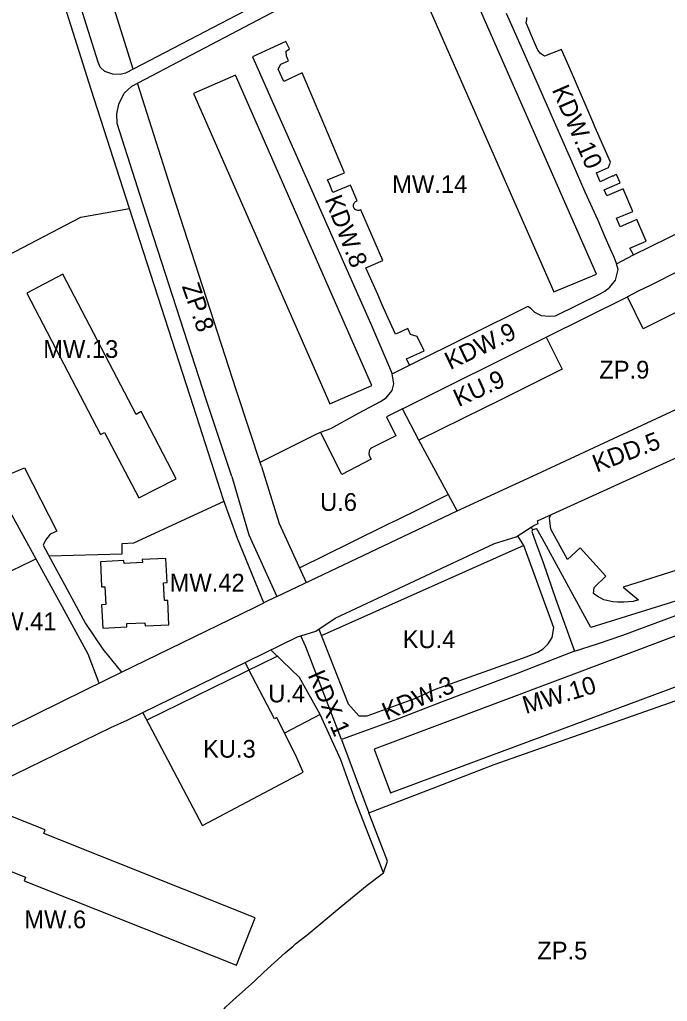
# Model space of a CAD drawing. Extents: x 7426178 to 7427732, y 5548847 to 5550287.
# Drawn here: x 7427061.4 to 7427225.9, y 5549279.8 to 5549528.9 of the extents above; entities that cross this region are included whole.
import ezdxf

# ---------------------------------------------------------------- set-up
doc = ezdxf.new("R2010")
doc.units = 0
for name, color, linetype in [('linie_rozgraniczajace', 7, 'Continuous'), ('linie_zabudowy_nieprzekraczalne', 7, 'Continuous'), ('linie_zabudowy_obowiazujace', 7, 'Continuous'), ('oznaczenia_przeznaczen', 7, 'Continuous')]:
    doc.layers.add(name, color=color, linetype=linetype)

msp = doc.modelspace()

# ---------------------------------------------------------------- linework, layer by layer
at = {"layer": 'linie_rozgraniczajace'}
for p, q in [((7427135.84, 5549509.04), (7427135.84, 5549509.04)), ((7427137.28, 5549505.68), (7427137.28, 5549505.68)), ((7427207.86, 5549500.83), (7427207.48, 5549501.69)), ((7427207.48, 5549501.69), (7427207.48, 5549501.69)), ((7427207.86, 5549500.83), (7427207.86, 5549500.83)), ((7427217.26, 5549469.25), (7427217.26, 5549469.25)), ((7427195.07, 5549448.37), (7427215.71, 5549458.63)), ((7427153.46, 5549456.57), (7427153.46, 5549456.57)), ((7427157.28, 5549449.31), (7427157.28, 5549449.31)), ((7427160.34, 5549441.22), (7427160.34, 5549441.22)), ((7427137.79, 5549424.28), (7427137.79, 5549424.28)), ((7427172.51, 5549404.3), (7427162.71, 5549422.19)), ((7427191.25, 5549400.11), (7427191.64, 5549399.49)), ((7427194.14, 5549397.18), (7427194.14, 5549397.18)), ((7427126.71, 5549382.6), (7427123.34, 5549380.95)), ((7427107.8, 5549324.47), (7427092.66, 5549353.13)), ((7427137.66, 5549352.59), (7427128.65, 5549347.91)), ((7427149.84, 5549348.75), (7427143.11, 5549346.29)), ((7427143.11, 5549346.29), (7427150.02, 5549327.69)), ((7427107.8, 5549324.47), (7427133.41, 5549338))]:
    msp.add_line(p, q, dxfattribs=at)
for points in [[(7427090.22, 5549516.36), (7427081.87, 5549542.92), (7427081.79, 5549544.97), (7427082.46, 5549552.09), (7427088.15, 5549602.17), (7427088.49, 5549610.35), (7427086.67, 5549624.17), (7427084.42, 5549632.79), (7427081.45, 5549642.76)], [(7427230.48, 5549589.38), (7427148.85, 5549546.95), (7427088.25, 5549515.33), (7427086.86, 5549515.01), (7427085.02, 5549515.09), (7427083.04, 5549515.77), (7427081.79, 5549516.82), (7427081.29, 5549518.09), (7427073.92, 5549541.54), (7427073.78, 5549545.19), (7427074.5, 5549552.91), (7427080.17, 5549602.79), (7427080.47, 5549609.99), (7427078.8, 5549622.63), (7427076.71, 5549630.64), (7427074.28, 5549638.8)], [(7427115.22, 5549413.02), (7427108.83, 5549432.27), (7427108.83, 5549432.27), (7427092.63, 5549482.16), (7427086.13, 5549502.57), (7427086.04, 5549505.04), (7427086.55, 5549507.51), (7427087.93, 5549510.29), (7427089.87, 5549512.02), (7427150.51, 5549543.92), (7427232.16, 5549586.41)], [(7427123.34, 5549380.95), (7427116.69, 5549397.29), (7427113.13, 5549407.11), (7427105.56, 5549430.76), (7427089.3, 5549481.03), (7427079.5, 5549511.18), (7427070.38, 5549540.22), (7427070.06, 5549553.47)], [(7427184.96, 5549530.59), (7427189.29, 5549520.68), (7427192.88, 5549512.63), (7427195.68, 5549506.27), (7427198.65, 5549499.56), (7427201.58, 5549492.85), (7427204.93, 5549485.26), (7427208.17, 5549478.05), (7427209.98, 5549473.84), (7427211.22, 5549470.95), (7427212.15, 5549468.89), (7427212.94, 5549467)], [(7427207.48, 5549501.69), (7427206.91, 5549502.99), (7427201.73, 5549515.02), (7427199.01, 5549521.35), (7427194.68, 5549519.69), (7427193.63, 5549520.34), (7427192.93, 5549521.15), (7427192.07, 5549523.26), (7427189.97, 5549528.11), (7427190.16, 5549528.92)], [(7427135.84, 5549509.04), (7427133.08, 5549515.46), (7427128.44, 5549513.26), (7427127.04, 5549516.38), (7427127.69, 5549517.61), (7427129.67, 5549518.51), (7427129.18, 5549519.69), (7427129.04, 5549520.96), (7427129.94, 5549521.5), (7427128.97, 5549523.39), (7427124.9, 5549521.5), (7427120.53, 5549519.45), (7427121.61, 5549517.02), (7427125.18, 5549508.99)], [(7427122.81, 5549415.54), (7427116.43, 5549434.77), (7427100.25, 5549484.61), (7427091.28, 5549512.76)], [(7427125.18, 5549508.99), (7427130.55, 5549496.81), (7427135.24, 5549486.35), (7427143.87, 5549466.83), (7427150.46, 5549451.93), (7427154.78, 5549441.85), (7427155.97, 5549439.08)], [(7427137.28, 5549505.68), (7427137.2, 5549505.87), (7427135.84, 5549509.04)], [(7427135.84, 5549509.04), (7427135.84, 5549509.04)], [(7427153.46, 5549456.57), (7427152.31, 5549459.17), (7427149.28, 5549465.93), (7427153.62, 5549467.83), (7427148.02, 5549480.65), (7427147.47, 5549480.49), (7427147.28, 5549480.47), (7427147.01, 5549480.54), (7427146.78, 5549480.66), (7427146.6, 5549480.77), (7427146.43, 5549480.96), (7427146.27, 5549481.18), (7427146.13, 5549481.55), (7427146.15, 5549481.91), (7427146.24, 5549482.22), (7427146.4, 5549482.51), (7427146.64, 5549482.74), (7427146.95, 5549482.9), (7427147.06, 5549482.93), (7427145.39, 5549486.91), (7427140.93, 5549485.02), (7427140.11, 5549486.99), (7427139.59, 5549488.25), (7427143.88, 5549490.08), (7427137.28, 5549505.68)], [(7427137.28, 5549505.68), (7427137.28, 5549505.68)], [(7427207.48, 5549501.69), (7427207.48, 5549501.69)], [(7427212.04, 5549489.25), (7427208.82, 5549487.77), (7427207.84, 5549490.02), (7427210.88, 5549491.38), (7427211.4, 5549492.79), (7427207.86, 5549500.83)], [(7427207.86, 5549500.83), (7427207.86, 5549500.83)], [(7427217.26, 5549469.25), (7427216.32, 5549470.93), (7427220.46, 5549472.71), (7427218.14, 5549478.18), (7427213.9, 5549476.35), (7427212.97, 5549478.51), (7427217.08, 5549480.26), (7427214.67, 5549486.03), (7427210.46, 5549484.18), (7427209.81, 5549485.7), (7427213.85, 5549487.51), (7427212.92, 5549489.65), (7427212.43, 5549489.43)], [(7427137.79, 5549424.28), (7427140.37, 5549425.18), (7427147.44, 5549429.1), (7427153.02, 5549432.02), (7427154.49, 5549432.94), (7427156, 5549434.84), (7427156.43, 5549436.51), (7427155.97, 5549439.08), (7427160.34, 5549441.22), (7427190.47, 5549456.21), (7427191.08, 5549455.72), (7427192.08, 5549454.67), (7427193.85, 5549453.84), (7427195.91, 5549453.65), (7427197.48, 5549453.77), (7427208.78, 5549459.32), (7427210, 5549460.06), (7427211.22, 5549461.02), (7427212.72, 5549462.85), (7427213.35, 5549465.51), (7427212.94, 5549467), (7427217.26, 5549469.25), (7427248.33, 5549484.49)], [(7427039.88, 5549459.54), (7427076.89, 5549478.82), (7427089.3, 5549481.03)], [(7427254.85, 5549478.08), (7427251.88, 5549476.6), (7427246.33, 5549473.85), (7427243.64, 5549472.52), (7427240.95, 5549471.19), (7427238.26, 5549469.86), (7427235.39, 5549468.41), (7427232.25, 5549466.85), (7427229.34, 5549465.41), (7427226.67, 5549464.08), (7427223.99, 5549462.75), (7427221.31, 5549461.42), (7427218.63, 5549460.09), (7427215.71, 5549458.63)], [(7427258.91, 5549469.96), (7427239.47, 5549460.24), (7427236.31, 5549458.73), (7427219.73, 5549450.51), (7427215.71, 5549458.63)], [(7427081.6, 5549360.57), (7427078.79, 5549367.94), (7427072.68, 5549379.11), (7427058.93, 5549404.03), (7427047.75, 5549425.49), (7427038.72, 5549443.34), (7427032.67, 5549455.78), (7427026.1, 5549452.36)], [(7427157.28, 5549449.31), (7427156.81, 5549449.1), (7427154.55, 5549454.13), (7427153.46, 5549456.57)], [(7427153.46, 5549456.57), (7427153.46, 5549456.57)], [(7427160.34, 5549441.22), (7427159.63, 5549442.85), (7427164.07, 5549444.87), (7427162.31, 5549448.51), (7427160.65, 5549449.05), (7427159.96, 5549450.52), (7427157.28, 5549449.31)], [(7427157.28, 5549449.31), (7427157.28, 5549449.31)], [(7427172.51, 5549404.3), (7427192.72, 5549413.62), (7427247.52, 5549439.05), (7427269.86, 5549449.36)], [(7427191.99, 5549400.58), (7427193.09, 5549401.11), (7427192.87, 5549401.78), (7427270.54, 5549437.01)], [(7427158.59, 5549430.21), (7427154.55, 5549428.14), (7427156.89, 5549423.32), (7427150.78, 5549420.29), (7427150.45, 5549420.06), (7427150.23, 5549419.78), (7427150.1, 5549419.44), (7427150.05, 5549418.75), (7427150.14, 5549418.3), (7427150.63, 5549417.39), (7427143.17, 5549413.51), (7427137.79, 5549424.28)], [(7427122.45, 5549416.63), (7427136.18, 5549423.47), (7427137.79, 5549424.28)], [(7427059.42, 5549413.84), (7427062.59, 5549415.17), (7427070.78, 5549399.15), (7427069.14, 5549398.34), (7427067.9, 5549396.82), (7427067.38, 5549395.62), (7427069.83, 5549391.04), (7427072.85, 5549385.41), (7427078.09, 5549375.69), (7427082.51, 5549369.19), (7427087.23, 5549363.32), (7427120.98, 5549379.8), (7427123.34, 5549380.95)], [(7427122.81, 5549415.54), (7427127.29, 5549401.05), (7427134.1, 5549386.11)], [(7427115.22, 5549413.02), (7427119.61, 5549398.18), (7427126.71, 5549382.6), (7427170.68, 5549403.49), (7427172.51, 5549404.3)], [(7427068.85, 5549392.87), (7427087.39, 5549393.37), (7427087.41, 5549395.99), (7427090.39, 5549396.16), (7427113.27, 5549406.72)], [(7427307.84, 5549403.48), (7427294.24, 5549397.88), (7427290.18, 5549396.65), (7427275.57, 5549393.25), (7427268.93, 5549391.83), (7427254.5, 5549388.59), (7427237.89, 5549384.43), (7427229.28, 5549381.76), (7427206.45, 5549374.66), (7427194.14, 5549397.18)], [(7427238.13, 5549392.37), (7427214.65, 5549384.89), (7427218.57, 5549381.71), (7427217.17, 5549381.32), (7427214.77, 5549381.11), (7427213.19, 5549381.08), (7427212.05, 5549381.19), (7427209.75, 5549381.75), (7427208.04, 5549382.64), (7427207.14, 5549383.3), (7427207.27, 5549384.86), (7427210.22, 5549387.73), (7427203.69, 5549394.92), (7427200.51, 5549391.94), (7427196.26, 5549399.63), (7427195.92, 5549402.56), (7427196.23, 5549403.3)], [(7427132.78, 5549372.59), (7427136.57, 5549373.75), (7427141.46, 5549377.03), (7427182, 5549396.02), (7427187.5, 5549397.71), (7427191.25, 5549400.11), (7427191.99, 5549400.58)], [(7427137.31, 5549374.25), (7427144.79, 5549355.29), (7427147.47, 5549352.29), (7427149.61, 5549352.24), (7427161.71, 5549356.72), (7427166.97, 5549359.03), (7427190.28, 5549367.33), (7427192.98, 5549368.41), (7427194.3, 5549369.26), (7427195.63, 5549370.57), (7427196.57, 5549372.15), (7427197.01, 5549374.6), (7427189.43, 5549395.46), (7427187.87, 5549397.95)], [(7427194.14, 5549397.18), (7427192.83, 5549399.53), (7427192.53, 5549399.7), (7427191.64, 5549399.49), (7427191.4, 5549399.04), (7427192.35, 5549396.47), (7427194.36, 5549391.22), (7427197.43, 5549382.05), (7427202.31, 5549368.66), (7427199.23, 5549367.54), (7427187.98, 5549363.14), (7427168.67, 5549355.8), (7427157.29, 5549351.47), (7427149.84, 5549348.75)], [(7427208.1, 5549370.51), (7427214.58, 5549372.79), (7427231.65, 5549379.05), (7427239.19, 5549381.81), (7427246.05, 5549383.91), (7427253.06, 5549385.54), (7427269.91, 5549389.18), (7427301.72, 5549396.43), (7427304.78, 5549397.3), (7427305.44, 5549394.04)], [(7427034.04, 5549379.24), (7427037.74, 5549380.71), (7427042.75, 5549382.08), (7427047.76, 5549383.46), (7427049.11, 5549384.26), (7427054.36, 5549386.77), (7427064.27, 5549391.56), (7427065.49, 5549392.15)], [(7427111.3, 5549275.29), (7427112.42, 5549276.71), (7427113.63, 5549278.4), (7427115.63, 5549280.17), (7427121.01, 5549284.98), (7427123.37, 5549287.21), (7427128.8, 5549292.12), (7427130.82, 5549293.83), (7427131.43, 5549294.45), (7427134.33, 5549296.6), (7427143.02, 5549303.88), (7427149.6, 5549309.36), (7427153.81, 5549312.46), (7427154.8, 5549315.39), (7427150.02, 5549327.69), (7427166.15, 5549333.81), (7427181.85, 5549339.96), (7427249.51, 5549363.69), (7427309.23, 5549379.16)], [(7427088.82, 5549351.24), (7427111.03, 5549362.11), (7427131.9, 5549372.32), (7427132.78, 5549372.59)], [(7427143.11, 5549346.29), (7427134.08, 5549369.8), (7427132.78, 5549372.59)], [(7427202.31, 5549368.66), (7427208.1, 5549370.51)], [(7427137.66, 5549352.59), (7427132.41, 5549361.99), (7427128.05, 5549366.21), (7427125.15, 5549369.02)], [(7427133.41, 5549338), (7427131.44, 5549342.41), (7427128.65, 5549347.91), (7427126.67, 5549351.83), (7427126.06, 5549351.51), (7427123.28, 5549356.83), (7427120.49, 5549362.14), (7427118.6, 5549365.81)], [(7427041.83, 5549341.06), (7427059.03, 5549349.51), (7427078.08, 5549358.85), (7427087.23, 5549363.32)], [(7427013.13, 5549268.92), (7427005.61, 5549291.59), (7427005.47, 5549294.05), (7427002.49, 5549302.88), (7427002.29, 5549306.24), (7427003.23, 5549308.53), (7427005.69, 5549310.69), (7427031.81, 5549323.48), (7427048.39, 5549331.54), (7427056.79, 5549335.77), (7427084.49, 5549349.29), (7427088.69, 5549351.18), (7427088.82, 5549351.24)], [(7427153.81, 5549312.46), (7427146.75, 5549330.48), (7427142.95, 5549341.1), (7427137.66, 5549352.59)]]:
    msp.add_lwpolyline(points, dxfattribs=at)
msp.add_lwpolyline([(7427195.07, 5549448.37), (7427199.12, 5549440.27), (7427182.59, 5549431.99), (7427179.27, 5549430.38), (7427162.71, 5549422.19), (7427158.59, 5549430.21), (7427175.17, 5549438.46), (7427178.53, 5549440.08)], close=True, dxfattribs=at)
for centre, start, end in [((7427190.48, 5549529.12), 119.6907, 211.3515), ((7427212.11, 5549489.62), 259.5072, 329.7592)]:
    msp.add_arc(centre, 0.375, start, end, dxfattribs=at)
at = {"layer": 'linie_zabudowy_nieprzekraczalne'}
for p, q in [((7427189.43, 5549395.46), (7427137.97, 5549372.59)), ((7427119.88, 5549363.33), (7427119.88, 5549363.33))]:
    msp.add_line(p, q, dxfattribs=at)
for points in [[(7427132.41, 5549389.83), (7427145.63, 5549396.34), (7427155.02, 5549400.97), (7427157.27, 5549402), (7427162.94, 5549404.83), (7427170.22, 5549408.47)], [(7427126.84, 5549367.38), (7427093.7, 5549351.16)]]:
    msp.add_lwpolyline(points, dxfattribs=at)
at = {"layer": 'linie_zabudowy_obowiazujace'}
msp.add_line((7427098.53, 5549392.22), (7427092.51, 5549391.92), dxfattribs=at)
for points in [[(7427162.46, 5549538.41), (7427197.02, 5549459.84), (7427207.9, 5549464.38), (7427173.12, 5549543.27), (7427162.46, 5549538.41)], [(7427105.54, 5549510.19), (7427140.15, 5549431.41), (7427150.78, 5549436.08), (7427116.17, 5549514.86), (7427105.54, 5549510.19)], [(7427063.18, 5549459.56), (7427081.87, 5549423.65), (7427082.95, 5549424.19), (7427091.64, 5549407.57), (7427101.11, 5549412.42), (7427092.22, 5549429.53), (7427090.92, 5549428.77), (7427072.37, 5549464.35), (7427063.18, 5549459.56)], [(7427092.51, 5549391.92), (7427092.54, 5549391.2), (7427087.88, 5549390.97), (7427087.84, 5549391.68), (7427081.88, 5549391.38), (7427082.2, 5549384.99)], [(7427082.2, 5549384.99), (7427083.03, 5549385.03), (7427083.26, 5549380.5), (7427082.19, 5549380.45), (7427082.49, 5549374.54), (7427088.61, 5549374.85), (7427088.57, 5549375.69), (7427093.16, 5549375.92), (7427093.21, 5549375.08), (7427099.28, 5549375.38), (7427098.97, 5549381.58), (7427098.15, 5549381.54), (7427097.92, 5549386.05), (7427098.84, 5549386.1), (7427098.53, 5549392.22)], [(7427244.03, 5549378.6), (7427151.37, 5549343.86), (7427155.52, 5549332.77), (7427248.12, 5549367.2), (7427307.4, 5549380.55), (7427304.83, 5549392.09), (7427244.03, 5549378.6)], [(7427067.51, 5549322.41), (7427067.88, 5549323.34), (7427053.99, 5549328.86), (7427049.18, 5549316.78), (7427062.89, 5549311.33), (7427062.52, 5549310.41), (7427116.42, 5549288.99), (7427121.22, 5549301.07), (7427067.51, 5549322.41)]]:
    msp.add_lwpolyline(points, dxfattribs=at)

# ---------------------------------------------------------------- texts
at = {"layer": 'oznaczenia_przeznaczen'}
for s, rotation, p in [('KDW.10', 293.651, (7427196.46, 5549511.13)), ('KDW.8', 291.3616, (7427138.75, 5549483.34)), ('ZP.8', 289.1682, (7427102.53, 5549461.27)), ('KDW.9', 25.6359, (7427170.7, 5549439.98)), ('KU.9', 24.3559, (7427172.82, 5549430.59)), ('KDD.5', 20.7864, (7427207.9, 5549413.98)), ('KDX.1', 293.6279, (7427134.45, 5549362.62)), ('KDW.3', 22.8177, (7427154.6, 5549351.05)), ('MW.10', 16.788, (7427189.89, 5549352.72))]:
    msp.add_text(s, height=4.5, rotation=rotation, dxfattribs=at).set_placement(p)
for s, p in [('MW.14', (7427155.98, 5549484.92)), ('MW.13', (7427067.36, 5549443.1)), ('ZP.9', (7427208.57, 5549437.86)), ('U.6', (7427137.67, 5549404.28)), ('MW.42', (7427099.46, 5549383.82)), ('MW.41', (7427051.68, 5549374)), ('KU.4', (7427158.65, 5549369.46)), ('U.4', (7427124.5, 5549355.7)), ('KU.3', (7427107.94, 5549341.67)), ('MW.6', (7427062.55, 5549298.4)), ('ZP.5', (7427192.81, 5549290.47))]:
    msp.add_text(s, height=4.5, dxfattribs=at).set_placement(p)

doc.saveas('drawing.dxf')
